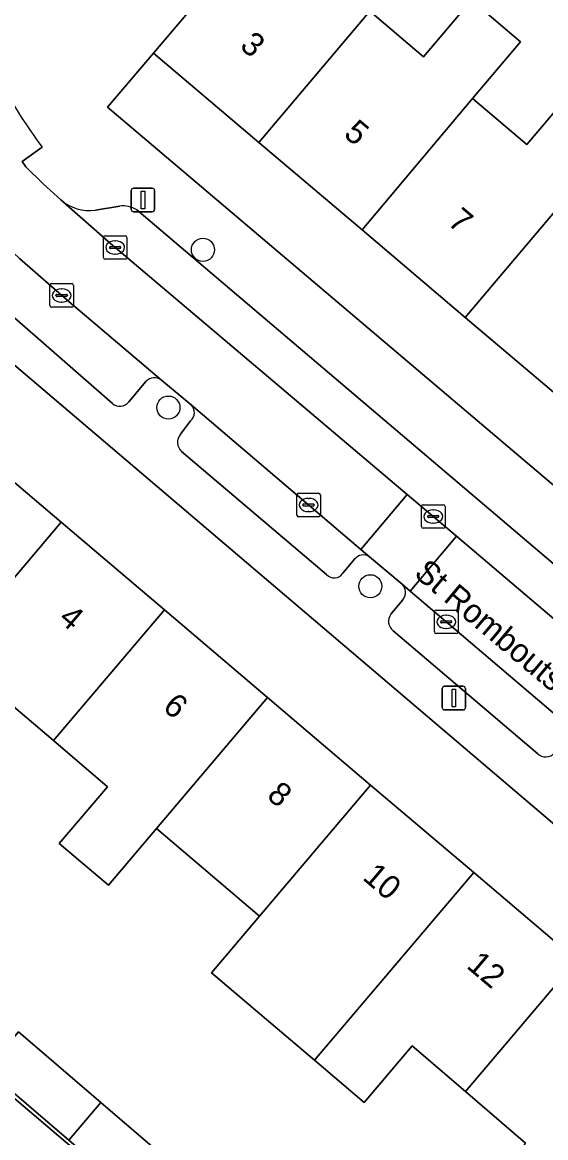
# Model space of a CAD drawing. Extents: x 162523 to 163266, y 381230 to 382050.
# Drawn here: x 162807.67 to 162829.88, y 381623.52 to 381670.82 of the extents above; entities that cross this region are included whole.
import ezdxf

# ---------------------------------------------------------------- set-up
doc = ezdxf.new("R2010")
doc.units = 0
for name, color, linetype in [('IMGEO_Boom', 7, 'Continuous'), ('IMGEO_Erf', 7, 'Continuous'), ('IMGEO_Kolk', 7, 'Continuous'), ('IMGEO_Lichtmast', 7, 'Continuous'), ('IMGEO_Openbare_ruimte_label', 7, 'Continuous'), ('IMGEO_Pand', 7, 'Continuous'), ('IMGEO_Pand_nummerreeks', 7, 'Continuous'), ('IMGEO_Parkeervlak_open', 7, 'Continuous'), ('IMGEO_Rijbaan_lokaal_open', 7, 'Continuous'), ('IMGEO_Voetpad_open', 7, 'Continuous')]:
    doc.layers.add(name, color=color, linetype=linetype)

msp = doc.modelspace()

# ---------------------------------------------------------------- linework, layer by layer
at = {"layer": 'IMGEO_Boom'}
for centre in [(162815.332, 381661.173), (162813.869, 381654.484), (162822.437, 381646.905)]:
    msp.add_circle(centre, 0.489, dxfattribs=at)
at = {"layer": 'IMGEO_Erf'}
for points in [[(162822.416, 381671.289), (162824.693, 381669.36), (162826.729, 381671.763), (162828.812, 381669.998), (162826.776, 381667.595), (162829.081, 381665.642), (162831.117, 381668.045)], [(162829.017, 381623.287), (162826.477, 381625.484), (162824.213, 381627.409), (162822.173, 381625.011), (162820.066, 381626.801), (162818.218, 381628.37), (162815.691, 381630.516), (162817.732, 381632.92), (162813.366, 381636.633), (162811.32, 381634.226), (162809.238, 381635.993), (162811.286, 381638.402), (162808.987, 381640.357), (162806.725, 381642.28)], [(162796.51, 381634.375), (162822.847, 381611.985)]]:
    msp.add_lwpolyline(points, dxfattribs=at)
for points in [[(162830.842, 381654.594), (162826.462, 381658.305), (162822.083, 381662.016), (162817.704, 381665.727), (162813.228, 381669.519), (162811.287, 381667.219), (162850.914, 381633.649), (162852.914, 381635.892), (162848.359, 381639.752), (162843.98, 381643.462), (162839.6, 381647.173), (162835.221, 381650.884)], [(162807.327, 381656.293), (162804.867, 381653.4), (162809.322, 381649.618), (162813.697, 381645.903), (162818.073, 381642.188), (162822.448, 381638.473), (162826.824, 381634.758), (162831.199, 381631.044), (162835.786, 381627.149), (162838.227, 381630.019)], [(162811.005, 381625.012), (162814.582, 381621.949), (162813.221, 381620.346), (162809.644, 381623.41), (162806.14, 381626.412), (162807.501, 381628.014)]]:
    msp.add_lwpolyline(points, close=True, dxfattribs=at)
at = {"layer": 'IMGEO_Kolk'}
for p, q in [((162811.108, 381660.845), (162811.108, 381661.697)), ((162811.183, 381661.771), (162812.035, 381661.771)), ((162811.596, 381661.551), (162811.621, 381661.551)), ((162812.109, 381661.697), (162812.109, 381660.845)), ((162811.367, 381661.265), (162811.367, 381661.277)), ((162811.805, 381661.228), (162811.407, 381661.228)), ((162811.41, 381661.314), (162811.808, 381661.314)), ((162811.619, 381660.991), (162811.594, 381660.991)), ((162811.851, 381661.277), (162811.851, 381661.265)), ((162812.035, 381660.771), (162811.183, 381660.771)), ((162808.837, 381658.812), (162808.837, 381659.664)), ((162808.912, 381659.738), (162809.764, 381659.738)), ((162809.325, 381659.518), (162809.35, 381659.518)), ((162809.838, 381659.664), (162809.838, 381658.812)), ((162809.096, 381659.232), (162809.096, 381659.244)), ((162809.534, 381659.195), (162809.136, 381659.195)), ((162809.139, 381659.281), (162809.537, 381659.281)), ((162809.58, 381659.244), (162809.58, 381659.232)), ((162809.764, 381658.738), (162808.912, 381658.738)), ((162809.348, 381658.958), (162809.323, 381658.958)), ((162819.316, 381649.925), (162819.316, 381650.777)), ((162819.391, 381650.851), (162820.243, 381650.851)), ((162819.804, 381650.631), (162819.829, 381650.631)), ((162820.317, 381650.777), (162820.317, 381649.925)), ((162819.575, 381650.345), (162819.575, 381650.357)), ((162820.013, 381650.308), (162819.615, 381650.308)), ((162819.618, 381650.394), (162820.016, 381650.394)), ((162819.827, 381650.071), (162819.802, 381650.071)), ((162820.059, 381650.357), (162820.059, 381650.345)), ((162824.605, 381649.437), (162824.605, 381650.289)), ((162824.68, 381650.363), (162825.532, 381650.363)), ((162825.093, 381650.143), (162825.118, 381650.143)), ((162825.606, 381650.289), (162825.606, 381649.437)), ((162820.243, 381649.851), (162819.391, 381649.851)), ((162824.864, 381649.857), (162824.864, 381649.869)), ((162825.302, 381649.82), (162824.904, 381649.82)), ((162824.907, 381649.906), (162825.305, 381649.906)), ((162825.116, 381649.583), (162825.091, 381649.583)), ((162825.348, 381649.869), (162825.348, 381649.857)), ((162825.532, 381649.363), (162824.68, 381649.363)), ((162825.157, 381644.969), (162825.157, 381645.821)), ((162825.232, 381645.895), (162826.084, 381645.895)), ((162826.158, 381645.821), (162826.158, 381644.969)), ((162825.416, 381645.389), (162825.416, 381645.401)), ((162825.854, 381645.352), (162825.456, 381645.352)), ((162825.459, 381645.438), (162825.857, 381645.438)), ((162825.645, 381645.675), (162825.67, 381645.675)), ((162825.9, 381645.401), (162825.9, 381645.389)), ((162826.084, 381644.895), (162825.232, 381644.895)), ((162825.668, 381645.115), (162825.643, 381645.115))]:
    msp.add_line(p, q, dxfattribs=at)
for points in [[(162811.108, 381660.845), (162811.108, 381661.697)], [(162811.183, 381661.771), (162812.035, 381661.771)], [(162812.109, 381661.697), (162812.109, 381660.845)], [(162812.035, 381660.771), (162811.183, 381660.771)], [(162808.837, 381658.812), (162808.837, 381659.664)], [(162808.912, 381659.738), (162809.764, 381659.738)], [(162809.838, 381659.664), (162809.838, 381658.812)], [(162809.764, 381658.738), (162808.912, 381658.738)], [(162819.316, 381649.925), (162819.316, 381650.777)], [(162819.391, 381650.851), (162820.243, 381650.851)], [(162820.317, 381650.777), (162820.317, 381649.925)], [(162824.605, 381649.437), (162824.605, 381650.289)], [(162824.68, 381650.363), (162825.532, 381650.363)], [(162825.606, 381650.289), (162825.606, 381649.437)], [(162820.243, 381649.851), (162819.391, 381649.851)], [(162825.532, 381649.363), (162824.68, 381649.363)], [(162825.157, 381644.969), (162825.157, 381645.821)], [(162825.232, 381645.895), (162826.084, 381645.895)], [(162826.158, 381645.821), (162826.158, 381644.969)], [(162826.084, 381644.895), (162825.232, 381644.895)]]:
    msp.add_lwpolyline(points, dxfattribs=at)
for centre, radius, start, end in [((162811.185, 381661.695), 0.0765, 91.552, 178.448), ((162811.185, 381661.695), 0.0765, 91.552, 178.448), ((162812.033, 381661.695), 0.0765, 1.552, 88.448), ((162812.033, 381661.695), 0.0765, 1.552, 88.448), ((162811.407, 381661.274), 0.0403, 85.8775, 175.7526), ((162811.404, 381661.264), 0.0366, 178.938, 274.7102), ((162811.808, 381661.271), 0.043, 264.8664, 352.4533), ((162811.812, 381661.276), 0.0386, 1.7309, 96.639), ((162811.185, 381660.847), 0.0765, 181.552, 268.448), ((162811.185, 381660.847), 0.0765, 181.552, 268.448), ((162812.033, 381660.847), 0.0765, 271.552, 358.448), ((162812.033, 381660.847), 0.0765, 271.552, 358.448), ((162808.914, 381659.662), 0.0765, 91.552, 178.448), ((162808.914, 381659.662), 0.0765, 91.552, 178.448), ((162809.762, 381659.662), 0.0765, 1.552, 88.448), ((162809.762, 381659.662), 0.0765, 1.552, 88.448), ((162809.136, 381659.241), 0.0403, 85.8775, 175.7526), ((162809.133, 381659.231), 0.0366, 178.938, 274.7102), ((162809.537, 381659.238), 0.043, 264.8664, 352.4533), ((162809.541, 381659.243), 0.0386, 1.7309, 96.639), ((162808.914, 381658.814), 0.0765, 181.552, 268.448), ((162808.914, 381658.814), 0.0765, 181.552, 268.448), ((162809.762, 381658.814), 0.0765, 271.552, 358.448), ((162809.762, 381658.814), 0.0765, 271.552, 358.448), ((162819.393, 381650.775), 0.0765, 91.552, 178.448), ((162819.393, 381650.775), 0.0765, 91.552, 178.448), ((162820.241, 381650.775), 0.0765, 1.552, 88.448), ((162820.241, 381650.775), 0.0765, 1.552, 88.448), ((162819.615, 381650.354), 0.0403, 85.8775, 175.7526), ((162819.612, 381650.344), 0.0366, 178.938, 274.7102), ((162820.016, 381650.351), 0.043, 264.8664, 352.4533), ((162820.02, 381650.356), 0.0386, 1.7309, 96.639), ((162824.682, 381650.287), 0.0765, 91.552, 178.448), ((162824.682, 381650.287), 0.0765, 91.552, 178.448), ((162825.53, 381650.287), 0.0765, 1.552, 88.448), ((162825.53, 381650.287), 0.0765, 1.552, 88.448), ((162819.393, 381649.927), 0.0765, 181.552, 268.448), ((162819.393, 381649.927), 0.0765, 181.552, 268.448), ((162820.241, 381649.927), 0.0765, 271.552, 358.448), ((162820.241, 381649.927), 0.0765, 271.552, 358.448), ((162824.904, 381649.866), 0.0403, 85.8775, 175.7526), ((162824.901, 381649.856), 0.0366, 178.938, 274.7102), ((162825.305, 381649.863), 0.043, 264.8664, 352.4533), ((162825.309, 381649.868), 0.0386, 1.7309, 96.639), ((162824.682, 381649.439), 0.0765, 181.552, 268.448), ((162824.682, 381649.439), 0.0765, 181.552, 268.448), ((162825.53, 381649.439), 0.0765, 271.552, 358.448), ((162825.53, 381649.439), 0.0765, 271.552, 358.448), ((162825.234, 381645.819), 0.0765, 91.552, 178.448), ((162825.234, 381645.819), 0.0765, 91.552, 178.448), ((162826.082, 381645.819), 0.0765, 1.552, 88.448), ((162826.082, 381645.819), 0.0765, 1.552, 88.448), ((162825.456, 381645.398), 0.0403, 85.8775, 175.7526), ((162825.453, 381645.388), 0.0366, 178.938, 274.7102), ((162825.857, 381645.395), 0.043, 264.8664, 352.4533), ((162825.861, 381645.4), 0.0386, 1.7309, 96.639), ((162825.234, 381644.971), 0.0765, 181.552, 268.448), ((162825.234, 381644.971), 0.0765, 181.552, 268.448), ((162826.082, 381644.971), 0.0765, 271.552, 358.448), ((162826.082, 381644.971), 0.0765, 271.552, 358.448)]:
    msp.add_arc(centre, radius, start, end, dxfattribs=at)
for centre, major_axis, ratio, start_param, end_param in [((162811.595, 381661.271), (-0.387, 0.002), 0.722429, 4.712389, 7.853982), ((162811.62, 381661.271), (-0.39, 0.002), 0.717154, 1.570796, 4.712389), ((162809.324, 381659.238), (-0.387, 0.002), 0.722429, 4.712389, 7.853982), ((162809.349, 381659.238), (-0.39, 0.002), 0.717154, 1.570796, 4.712389), ((162819.803, 381650.351), (-0.387, 0.002), 0.722429, 4.712389, 7.853982), ((162819.828, 381650.351), (-0.39, 0.002), 0.717154, 1.570796, 4.712389), ((162825.092, 381649.863), (-0.387, 0.002), 0.722429, 4.712389, 7.853982), ((162825.117, 381649.863), (-0.39, 0.002), 0.717154, 1.570796, 4.712389), ((162825.644, 381645.395), (-0.387, 0.002), 0.722429, 4.712389, 7.853982), ((162825.669, 381645.395), (-0.39, 0.002), 0.717154, 1.570796, 4.712389)]:
    msp.add_ellipse(centre, major_axis=major_axis, ratio=ratio, start_param=start_param, end_param=end_param, dxfattribs=at)
at = {"layer": 'IMGEO_Lichtmast'}
for p, q in [((162812.393, 381663.787), (162813.183, 381663.787)), ((162813.183, 381663.787), (162812.393, 381663.787)), ((162812.293, 381662.887), (162812.293, 381663.687)), ((162812.293, 381663.687), (162812.293, 381662.887)), ((162813.283, 381663.687), (162813.283, 381662.887)), ((162813.283, 381662.887), (162813.283, 381663.687)), ((162813.183, 381662.787), (162812.393, 381662.787)), ((162812.393, 381662.787), (162813.183, 381662.787)), ((162825.485, 381641.762), (162825.485, 381642.562)), ((162825.485, 381642.562), (162825.485, 381641.762)), ((162825.585, 381642.662), (162826.375, 381642.662)), ((162826.375, 381642.662), (162825.585, 381642.662)), ((162826.475, 381642.562), (162826.475, 381641.762)), ((162826.475, 381641.762), (162826.475, 381642.562)), ((162826.375, 381641.662), (162825.585, 381641.662)), ((162825.585, 381641.662), (162826.375, 381641.662))]:
    msp.add_line(p, q, dxfattribs=at)
for points in [[(162812.713, 381663.662), (162812.863, 381663.662), (162812.863, 381662.912), (162812.713, 381662.912), (162812.713, 381663.662)], [(162825.905, 381642.537), (162826.055, 381642.537), (162826.055, 381641.787), (162825.905, 381641.787), (162825.905, 381642.537)]]:
    msp.add_lwpolyline(points, dxfattribs=at)
for centre, start, end in [((162812.393, 381663.687), 90, 180), ((162812.393, 381663.687), 90, 180), ((162813.183, 381663.687), 0, 90), ((162813.183, 381663.687), 360, 90), ((162812.393, 381662.887), 180, 270), ((162812.393, 381662.887), 180, 270), ((162813.183, 381662.887), 270, 0), ((162813.183, 381662.887), 270, 0), ((162825.585, 381642.562), 90, 180), ((162825.585, 381642.562), 90, 180), ((162826.375, 381642.562), 0, 90), ((162826.375, 381642.562), 360, 90), ((162825.585, 381641.762), 180, 270), ((162825.585, 381641.762), 180, 270), ((162826.375, 381641.762), 270, 0), ((162826.375, 381641.762), 270, 0)]:
    msp.add_arc(centre, 0.1, start, end, dxfattribs=at)
at = {"layer": 'IMGEO_Pand'}
for points in [[(162817.704, 381665.727), (162822.416, 381671.289), (162817.941, 381675.081), (162816.461, 381673.334), (162815.562, 381672.274), (162813.228, 381669.519)], [(162826.776, 381667.595), (162828.812, 381669.998), (162826.729, 381671.763), (162824.693, 381669.36), (162822.416, 381671.289), (162817.704, 381665.727), (162822.083, 381662.016)], [(162826.462, 381658.305), (162833.211, 381666.271), (162831.117, 381668.045), (162829.081, 381665.642), (162826.776, 381667.595), (162822.083, 381662.016)], [(162826.462, 381658.305), (162830.842, 381654.594), (162835.554, 381660.157), (162833.247, 381662.112), (162835.283, 381664.515), (162833.211, 381666.271)], [(162804.614, 381644.075), (162809.322, 381649.618), (162804.867, 381653.4), (162801.657, 381649.567), (162800.201, 381647.828)], [(162813.697, 381645.903), (162809.322, 381649.618), (162804.614, 381644.075), (162802.881, 381641.975), (162804.962, 381640.208), (162806.725, 381642.28), (162808.987, 381640.357)], [(162813.697, 381645.903), (162808.987, 381640.357), (162811.286, 381638.402), (162809.238, 381635.993), (162811.32, 381634.226), (162813.366, 381636.633), (162818.073, 381642.188)], [(162822.448, 381638.473), (162818.073, 381642.188), (162813.366, 381636.633), (162817.732, 381632.92)], [(162826.824, 381634.758), (162822.448, 381638.473), (162817.732, 381632.92), (162815.691, 381630.516), (162818.218, 381628.37), (162820.066, 381626.801)], [(162831.199, 381631.044), (162826.824, 381634.758), (162820.066, 381626.801), (162822.173, 381625.011), (162824.213, 381627.409), (162826.477, 381625.484)], [(162831.199, 381631.044), (162826.477, 381625.484), (162829.017, 381623.287), (162827.023, 381620.893), (162829.104, 381619.127), (162831.115, 381621.54), (162832.587, 381623.307), (162835.786, 381627.149)], [(162807.501, 381628.014), (162806.14, 381626.412), (162809.644, 381623.41), (162811.005, 381625.012)], [(162811.005, 381625.012), (162809.644, 381623.41), (162813.221, 381620.346), (162814.582, 381621.949)]]:
    msp.add_lwpolyline(points, close=True, dxfattribs=at)
at = {"layer": 'IMGEO_Parkeervlak_open'}
for points in [[(162809.303, 381663.293), (162811.413, 381661.436), (162823.995, 381650.801), (162825.09, 381649.875), (162826.092, 381649.024), (162869.033, 381612.565), (162871.13, 381610.785), (162906.436, 381580.866)], [(162811.8, 381663.026), (162810.77, 381662.858)], [(162906.836, 381582.885), (162905.255, 381584.216), (162896.818, 381591.315), (162893.937, 381593.76), (162871.782, 381612.563), (162826.436, 381651.063), (162812.522, 381662.862)], [(162809.65, 381658.966), (162807.552, 381660.807), (162805.425, 381662.797)], [(162804.623, 381660.648), (162811.491, 381654.659)], [(162813.578, 381655.64), (162809.65, 381658.966)], [(162812.189, 381654.721), (162812.908, 381655.589)], [(162822.404, 381648.149), (162822.027, 381648.47), (162814.832, 381654.599)], [(162814.805, 381653.918), (162814.376, 381653.355)], [(162814.427, 381652.619), (162820.581, 381647.402)], [(162821.269, 381647.455), (162821.768, 381648.047)], [(162831.43, 381640.494), (162824.128, 381646.697), (162823.781, 381646.991)], [(162823.813, 381646.33), (162823.31, 381645.72)], [(162823.401, 381645.011), (162829.539, 381639.799)]]:
    msp.add_lwpolyline(points, dxfattribs=at)
for centre, radius, start, end in [((162810.52, 381664.705), 1.864, 229.2544, 277.713), ((162811.925, 381661.907), 1.126, 58.0111, 96.3941), ((162813.271, 381655.242), 0.502, 52.3761, 136.3297), ((162811.81, 381655.024), 0.485, 228.8431, 321.3088), ((162814.509, 381654.271), 0.461, 310.0441, 45.415), ((162814.805, 381653.015), 0.548, 141.6259, 226.3019), ((162822.139, 381647.767), 0.465, 55.2373, 142.9854), ((162820.905, 381647.688), 0.432, 221.4126, 327.3975), ((162823.453, 381646.644), 0.478, 318.929, 46.6142), ((162823.722, 381645.412), 0.514, 143.2353, 231.3925), ((162829.874, 381640.152), 0.487, 226.4845, 320.2863)]:
    msp.add_arc(centre, radius, start, end, dxfattribs=at)
at = {"layer": 'IMGEO_Rijbaan_lokaal_open'}
for points in [[(162802.757, 381675.336), (162802.284, 381677.273), (162801.954, 381678.557), (162796.845, 381699.467), (162796.65, 381700.335), (162793.165, 381699.477), (162793.507, 381698.406), (162794.461, 381694.698), (162795.797, 381689.235), (162796.284, 381686.998), (162798.837, 381676.52), (162799.237, 381675.427), (162799.583, 381674.114), (162801.431, 381669.135), (162803.708, 381664.918), (162805.425, 381662.797), (162807.552, 381660.807), (162809.65, 381658.966), (162813.578, 381655.64), (162814.832, 381654.599), (162822.027, 381648.47), (162823.995, 381650.801), (162811.413, 381661.436)], [(162811.413, 381661.436), (162809.303, 381663.293), (162808.549, 381663.976), (162807.819, 381664.694), (162807.667, 381664.922)]]:
    msp.add_lwpolyline(points, dxfattribs=at)
for points in [[(162826.092, 381649.024), (162825.09, 381649.875), (162823.995, 381650.801), (162822.027, 381648.47), (162822.404, 381648.149), (162823.781, 381646.991), (162824.128, 381646.697)], [(162869.033, 381612.565), (162826.092, 381649.024), (162824.128, 381646.697), (162831.43, 381640.494), (162832.662, 381639.429), (162850.293, 381624.446), (162851.487, 381623.45), (162858.86, 381617.221), (162860.065, 381616.205), (162867.06, 381610.183)]]:
    msp.add_lwpolyline(points, close=True, dxfattribs=at)
at = {"layer": 'IMGEO_Voetpad_open'}
for points in [[(162852.007, 381632.723), (162850.914, 381633.649), (162811.287, 381667.219), (162813.228, 381669.519), (162815.562, 381672.274), (162814.451, 381673.234), (162812.033, 381675.291), (162809.626, 381677.339), (162807.22, 381679.387), (162805.722, 381680.662), (162803.738, 381688.547), (162800.78, 381700.348), (162800.493, 381701.494), (162801.406, 381705.07), (162799.576, 381710.347), (162798.548, 381713.754)], [(162822.847, 381611.985), (162796.51, 381634.375), (162792.035, 381638.152), (162792.178, 381638.353), (162793.831, 381640.283), (162800.201, 381647.828), (162801.657, 381649.567), (162804.867, 381653.4), (162807.327, 381656.293), (162805.837, 381657.564), (162805.796, 381657.517), (162804.096, 381655.524), (162800.858, 381651.715), (162799.816, 381650.49), (162791.576, 381640.722), (162747.24, 381678.307)], [(162807.667, 381664.922), (162808.505, 381665.53)], [(162808.505, 381665.53), (162807.667, 381664.922), (162807.819, 381664.694), (162808.549, 381663.976), (162809.303, 381663.293)], [(162810.77, 381662.858), (162811.8, 381663.026)], [(162812.522, 381662.862), (162826.436, 381651.063), (162871.782, 381612.563), (162893.937, 381593.76), (162894.26, 381594.141), (162897.141, 381591.696), (162896.818, 381591.315), (162905.255, 381584.216), (162906.836, 381582.885)], [(162811.491, 381654.659), (162804.623, 381660.648)], [(162805.837, 381657.564), (162807.327, 381656.293), (162838.227, 381630.019), (162839.377, 381629.041), (162870.268, 381602.775), (162871.412, 381601.803), (162900.572, 381577.383), (162901.643, 381578.628), (162892.144, 381586.646)], [(162812.908, 381655.589), (162812.189, 381654.721)], [(162814.832, 381654.599), (162813.578, 381655.64)], [(162814.376, 381653.355), (162814.805, 381653.918)], [(162820.581, 381647.402), (162814.427, 381652.619)], [(162821.768, 381648.047), (162821.269, 381647.455)], [(162823.781, 381646.991), (162822.404, 381648.149)], [(162823.31, 381645.72), (162823.813, 381646.33)], [(162829.539, 381639.799), (162823.401, 381645.011)]]:
    msp.add_lwpolyline(points, dxfattribs=at)
for centre, radius, start, end in [((162832.428, 381682.945), 29.591, 197.5239, 216.0526), ((162832.428, 381682.945), 29.591, 197.5239, 216.0526), ((162810.52, 381664.705), 1.864, 229.2544, 277.713), ((162811.925, 381661.907), 1.126, 58.0111, 96.3941), ((162813.271, 381655.242), 0.502, 52.3761, 136.3297), ((162811.81, 381655.024), 0.485, 228.8431, 321.3088), ((162814.509, 381654.271), 0.461, 310.0441, 45.415), ((162814.805, 381653.015), 0.548, 141.6259, 226.3019), ((162822.139, 381647.767), 0.465, 55.2373, 142.9854), ((162820.905, 381647.688), 0.432, 221.4126, 327.3975), ((162823.453, 381646.644), 0.478, 318.929, 46.6142), ((162823.722, 381645.412), 0.514, 143.2353, 231.3925), ((162829.874, 381640.152), 0.487, 226.4845, 320.2863)]:
    msp.add_arc(centre, radius, start, end, dxfattribs=at)

# ---------------------------------------------------------------- texts
at = {"layer": 'IMGEO_Openbare_ruimte_label'}
msp.add_text('St Romboutstraat', height=1, rotation=319.9083, dxfattribs=at).set_placement((162824.243, 381647.369))
at = {"layer": 'IMGEO_Pand_nummerreeks'}
for s, rotation, p in [('3', 319.7245, (162816.852, 381669.751)), ('5', 319.7245, (162821.261, 381666.015)), ('7', 319.7245, (162825.671, 381662.279)), ('4', 319.6679, (162809.16, 381645.453)), ('6', 319.6679, (162813.577, 381641.703)), ('8', 319.6679, (162817.997, 381637.95)), ('10', 319.6695, (162822.063, 381634.498)), ('12', 319.6679, (162826.475, 381630.752))]:
    msp.add_text(s, height=1, rotation=rotation, dxfattribs=at).set_placement(p)

doc.saveas('drawing.dxf')
